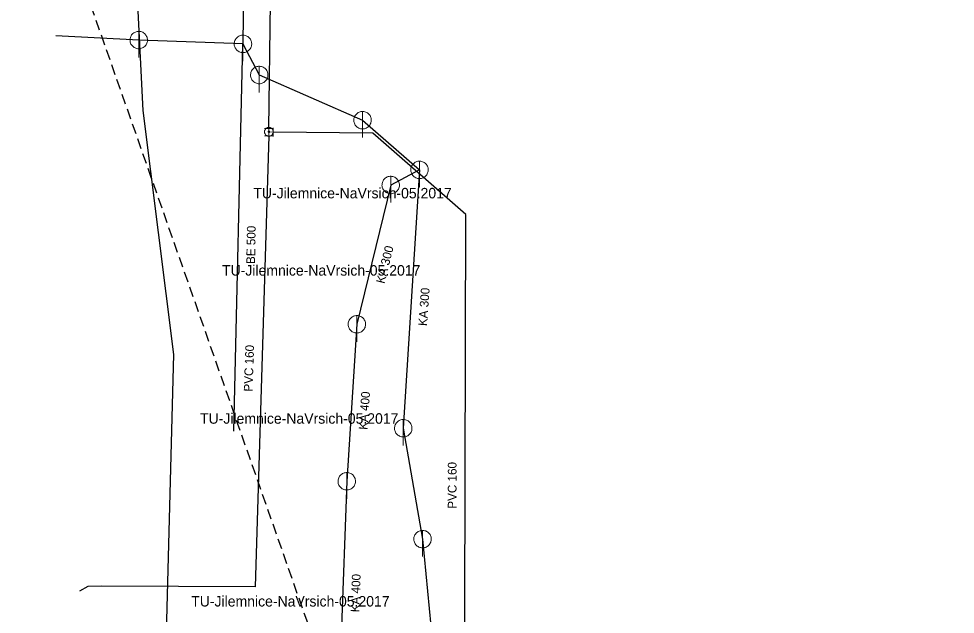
# Model space of a CAD drawing. Extents: x -659250 to -657316, y -997555 to -993684.
# Drawn here: x -658539.7 to -658432.4, y -995591.1 to -995522.9 of the extents above; entities that cross this region are included whole.
import ezdxf

# ---------------------------------------------------------------- set-up
doc = ezdxf.new("R2010")
doc.units = 0
doc.header["$LTSCALE"] = 0.4
doc.linetypes.add('MEDIUM_DASHED', pattern=[4.5, 3, -1.5])
doc.layers.add('1', color=7, linetype='Continuous')
for name, color, linetype, lineweight in [('14', 7, 'Continuous', 25), ('17', 7, 'Continuous', 25), ('22', 7, 'Continuous', 13), ('34', 7, 'Continuous', 13), ('47', 7, 'Continuous', 13), ('63', 7, 'MEDIUM_DASHED', 25)]:
    doc.layers.add(name, color=color, linetype=linetype, lineweight=lineweight)

msp = doc.modelspace()

# ---------------------------------------------------------------- linework, layer by layer
at = {"layer": '14'}
for p, q in [((-658515.1, -995570.149), (-658514.039, -995525.77)), ((-658514.039, -995525.77), (-658512.17, -995529.34)), ((-658512.17, -995529.34), (-658500.329, -995534.52)), ((-658500.329, -995534.52), (-658493.8, -995540.21)), ((-658493.8, -995540.21), (-658497.1, -995541.949)), ((-658493.8, -995540.21), (-658495.66, -995569.82)), ((-658497.1, -995541.949), (-658500.98, -995557.91)), ((-658500.98, -995557.91), (-658502.14, -995575.899)), ((-658495.66, -995569.82), (-658493.449, -995582.53)), ((-658502.14, -995575.899), (-658503, -995599.809)), ((-658493.449, -995582.53), (-658492.51, -995592.469))]:
    msp.add_line(p, q, dxfattribs=at)
at = {"layer": '14', "lineweight": 13}
msp.add_line((-658511.085, -995536.327), (-658511.068, -995535.851), dxfattribs=at)
at = {"layer": '14'}
msp.add_lwpolyline([(-658513.609, -995487.75), (-658514.039, -995525.77), (-658525.986, -995525.335), (-658535.481, -995524.836)], dxfattribs=at)
at = {"layer": '14', "lineweight": 13}
msp.add_lwpolyline([(-658510.582, -995535.879), (-658511.068, -995535.851), (-658511.067, -995535.467)], dxfattribs=at)
at = {"layer": '17'}
for points in [[(-658522.919, -995597.629), (-658521.967, -995561.364), (-658525.493, -995533.403), (-658526.434, -995514.37), (-658523.848, -995479.362), (-658526.669, -995461.504), (-658525.493, -995439.824), (-658524.877, -995415.208), (-658524.344, -995415.072)], [(-658511.067, -995535.467), (-658510.679, -995506.566), (-658511.949, -995476.057), (-658513.219, -995461.105), (-658519.998, -995427.785), (-658524.344, -995415.072)], [(-658511.085, -995536.327), (-658512.631, -995588.013), (-658530.219, -995587.906), (-658531.84, -995587.956), (-658532.794, -995588.487)], [(-658488.624, -995605.785), (-658488.504, -995545.309), (-658499.164, -995536.019), (-658510.582, -995535.879)]]:
    msp.add_lwpolyline(points, dxfattribs=at)
at = {"layer": '22'}
for p, q in [((-658525.986, -995527.336), (-658525.985, -995524.336)), ((-658514.039, -995527.77), (-658514.038, -995524.77)), ((-658512.17, -995531.34), (-658512.169, -995528.34)), ((-658500.329, -995536.52), (-658500.328, -995533.52)), ((-658493.8, -995542.21), (-658493.799, -995539.21)), ((-658497.1, -995543.949), (-658497.099, -995540.949)), ((-658500.98, -995559.91), (-658500.979, -995556.91)), ((-658495.66, -995571.82), (-658495.659, -995568.82)), ((-658502.14, -995577.899), (-658502.139, -995574.899)), ((-658493.449, -995584.53), (-658493.448, -995581.53))]:
    msp.add_line(p, q, dxfattribs=at)
for points in [[(-658524.986, -995525.336), (-658524.991, -995525.227), (-658525.009, -995525.119), (-658525.039, -995525.013), (-658525.079, -995524.912), (-658525.131, -995524.815), (-658525.193, -995524.725), (-658525.265, -995524.642), (-658525.345, -995524.568), (-658525.433, -995524.502), (-658525.527, -995524.447), (-658525.627, -995524.402), (-658525.732, -995524.369), (-658525.839, -995524.347), (-658525.948, -995524.337), (-658526.058, -995524.339), (-658526.166, -995524.353), (-658526.273, -995524.378), (-658526.376, -995524.415), (-658526.474, -995524.464), (-658526.566, -995524.522), (-658526.652, -995524.591), (-658526.729, -995524.668), (-658526.798, -995524.754), (-658526.857, -995524.846), (-658526.905, -995524.944), (-658526.942, -995525.047), (-658526.968, -995525.154), (-658526.982, -995525.262), (-658526.985, -995525.372), (-658526.975, -995525.481), (-658526.954, -995525.588), (-658526.92, -995525.692), (-658526.876, -995525.792), (-658526.821, -995525.887), (-658526.755, -995525.975), (-658526.681, -995526.055), (-658526.598, -995526.127), (-658526.508, -995526.189), (-658526.412, -995526.241), (-658526.31, -995526.282), (-658526.205, -995526.312), (-658526.097, -995526.33), (-658525.987, -995526.336), (-658525.878, -995526.33), (-658525.77, -995526.312), (-658525.665, -995526.283), (-658525.563, -995526.242), (-658525.466, -995526.19), (-658525.376, -995526.128), (-658525.293, -995526.057), (-658525.218, -995525.977), (-658525.153, -995525.889), (-658525.097, -995525.795), (-658525.053, -995525.695), (-658525.019, -995525.591), (-658524.997, -995525.483), (-658524.987, -995525.374)], [(-658513.039, -995525.77), (-658513.044, -995525.661), (-658513.062, -995525.553), (-658513.092, -995525.447), (-658513.132, -995525.346), (-658513.184, -995525.249), (-658513.246, -995525.159), (-658513.318, -995525.076), (-658513.398, -995525.002), (-658513.486, -995524.936), (-658513.58, -995524.881), (-658513.68, -995524.836), (-658513.785, -995524.803), (-658513.892, -995524.781), (-658514.001, -995524.771), (-658514.111, -995524.773), (-658514.219, -995524.787), (-658514.326, -995524.812), (-658514.429, -995524.849), (-658514.527, -995524.898), (-658514.619, -995524.956), (-658514.705, -995525.025), (-658514.782, -995525.102), (-658514.851, -995525.188), (-658514.91, -995525.28), (-658514.958, -995525.378), (-658514.995, -995525.481), (-658515.021, -995525.588), (-658515.035, -995525.696), (-658515.038, -995525.806), (-658515.028, -995525.915), (-658515.007, -995526.022), (-658514.973, -995526.126), (-658514.929, -995526.226), (-658514.874, -995526.321), (-658514.808, -995526.409), (-658514.734, -995526.489), (-658514.651, -995526.561), (-658514.561, -995526.623), (-658514.465, -995526.675), (-658514.363, -995526.716), (-658514.258, -995526.746), (-658514.15, -995526.764), (-658514.04, -995526.77), (-658513.931, -995526.764), (-658513.823, -995526.746), (-658513.718, -995526.717), (-658513.616, -995526.676), (-658513.519, -995526.624), (-658513.429, -995526.562), (-658513.346, -995526.491), (-658513.271, -995526.411), (-658513.206, -995526.323), (-658513.15, -995526.229), (-658513.106, -995526.129), (-658513.072, -995526.025), (-658513.05, -995525.917), (-658513.04, -995525.808)], [(-658511.17, -995529.34), (-658511.175, -995529.231), (-658511.193, -995529.123), (-658511.223, -995529.017), (-658511.263, -995528.916), (-658511.315, -995528.819), (-658511.377, -995528.729), (-658511.449, -995528.646), (-658511.529, -995528.572), (-658511.617, -995528.506), (-658511.711, -995528.451), (-658511.811, -995528.406), (-658511.916, -995528.373), (-658512.023, -995528.351), (-658512.132, -995528.341), (-658512.242, -995528.343), (-658512.35, -995528.357), (-658512.457, -995528.382), (-658512.56, -995528.419), (-658512.658, -995528.468), (-658512.75, -995528.526), (-658512.836, -995528.595), (-658512.913, -995528.672), (-658512.982, -995528.758), (-658513.041, -995528.85), (-658513.089, -995528.948), (-658513.126, -995529.051), (-658513.152, -995529.158), (-658513.166, -995529.266), (-658513.169, -995529.376), (-658513.159, -995529.485), (-658513.138, -995529.592), (-658513.104, -995529.696), (-658513.06, -995529.796), (-658513.005, -995529.891), (-658512.939, -995529.979), (-658512.865, -995530.059), (-658512.782, -995530.131), (-658512.692, -995530.193), (-658512.596, -995530.245), (-658512.494, -995530.286), (-658512.389, -995530.316), (-658512.281, -995530.334), (-658512.171, -995530.34), (-658512.062, -995530.334), (-658511.954, -995530.316), (-658511.849, -995530.287), (-658511.747, -995530.246), (-658511.65, -995530.194), (-658511.56, -995530.132), (-658511.477, -995530.061), (-658511.402, -995529.981), (-658511.337, -995529.893), (-658511.281, -995529.799), (-658511.237, -995529.699), (-658511.203, -995529.595), (-658511.181, -995529.487), (-658511.171, -995529.378)], [(-658499.329, -995534.52), (-658499.334, -995534.411), (-658499.352, -995534.303), (-658499.382, -995534.197), (-658499.422, -995534.096), (-658499.474, -995533.999), (-658499.536, -995533.909), (-658499.608, -995533.826), (-658499.688, -995533.752), (-658499.776, -995533.686), (-658499.87, -995533.631), (-658499.97, -995533.586), (-658500.075, -995533.553), (-658500.182, -995533.531), (-658500.291, -995533.521), (-658500.401, -995533.523), (-658500.509, -995533.537), (-658500.616, -995533.562), (-658500.719, -995533.599), (-658500.817, -995533.648), (-658500.909, -995533.706), (-658500.995, -995533.775), (-658501.072, -995533.852), (-658501.141, -995533.938), (-658501.2, -995534.03), (-658501.248, -995534.128), (-658501.285, -995534.231), (-658501.311, -995534.338), (-658501.325, -995534.446), (-658501.328, -995534.556), (-658501.318, -995534.665), (-658501.297, -995534.772), (-658501.263, -995534.876), (-658501.219, -995534.976), (-658501.164, -995535.071), (-658501.098, -995535.159), (-658501.024, -995535.239), (-658500.941, -995535.311), (-658500.851, -995535.373), (-658500.755, -995535.425), (-658500.653, -995535.466), (-658500.548, -995535.496), (-658500.44, -995535.514), (-658500.33, -995535.52), (-658500.221, -995535.514), (-658500.113, -995535.496), (-658500.008, -995535.467), (-658499.906, -995535.426), (-658499.809, -995535.374), (-658499.719, -995535.312), (-658499.636, -995535.241), (-658499.561, -995535.161), (-658499.496, -995535.073), (-658499.44, -995534.979), (-658499.396, -995534.879), (-658499.362, -995534.775), (-658499.34, -995534.667), (-658499.33, -995534.558)], [(-658492.8, -995540.21), (-658492.805, -995540.101), (-658492.823, -995539.993), (-658492.853, -995539.887), (-658492.893, -995539.786), (-658492.945, -995539.689), (-658493.007, -995539.599), (-658493.079, -995539.516), (-658493.159, -995539.442), (-658493.247, -995539.376), (-658493.341, -995539.321), (-658493.441, -995539.276), (-658493.546, -995539.243), (-658493.653, -995539.221), (-658493.762, -995539.211), (-658493.872, -995539.213), (-658493.98, -995539.227), (-658494.087, -995539.252), (-658494.19, -995539.289), (-658494.288, -995539.338), (-658494.38, -995539.396), (-658494.466, -995539.465), (-658494.543, -995539.542), (-658494.612, -995539.628), (-658494.671, -995539.72), (-658494.719, -995539.818), (-658494.756, -995539.921), (-658494.782, -995540.028), (-658494.796, -995540.136), (-658494.799, -995540.246), (-658494.789, -995540.355), (-658494.768, -995540.462), (-658494.734, -995540.566), (-658494.69, -995540.666), (-658494.635, -995540.761), (-658494.569, -995540.849), (-658494.495, -995540.929), (-658494.412, -995541.001), (-658494.322, -995541.063), (-658494.226, -995541.115), (-658494.124, -995541.156), (-658494.019, -995541.186), (-658493.911, -995541.204), (-658493.801, -995541.21), (-658493.692, -995541.204), (-658493.584, -995541.186), (-658493.479, -995541.157), (-658493.377, -995541.116), (-658493.28, -995541.064), (-658493.19, -995541.002), (-658493.107, -995540.931), (-658493.032, -995540.851), (-658492.967, -995540.763), (-658492.911, -995540.669), (-658492.867, -995540.569), (-658492.833, -995540.465), (-658492.811, -995540.357), (-658492.801, -995540.248)], [(-658496.1, -995541.949), (-658496.105, -995541.84), (-658496.123, -995541.732), (-658496.153, -995541.626), (-658496.193, -995541.525), (-658496.245, -995541.428), (-658496.307, -995541.338), (-658496.379, -995541.255), (-658496.459, -995541.181), (-658496.547, -995541.115), (-658496.641, -995541.06), (-658496.741, -995541.015), (-658496.846, -995540.982), (-658496.953, -995540.96), (-658497.062, -995540.95), (-658497.172, -995540.952), (-658497.28, -995540.966), (-658497.387, -995540.991), (-658497.49, -995541.028), (-658497.588, -995541.077), (-658497.68, -995541.135), (-658497.766, -995541.204), (-658497.843, -995541.281), (-658497.912, -995541.367), (-658497.971, -995541.459), (-658498.019, -995541.557), (-658498.056, -995541.66), (-658498.082, -995541.767), (-658498.096, -995541.875), (-658498.099, -995541.985), (-658498.089, -995542.094), (-658498.068, -995542.201), (-658498.034, -995542.305), (-658497.99, -995542.405), (-658497.935, -995542.5), (-658497.869, -995542.588), (-658497.795, -995542.668), (-658497.712, -995542.74), (-658497.622, -995542.802), (-658497.526, -995542.854), (-658497.424, -995542.895), (-658497.319, -995542.925), (-658497.211, -995542.943), (-658497.101, -995542.949), (-658496.992, -995542.943), (-658496.884, -995542.925), (-658496.779, -995542.896), (-658496.677, -995542.855), (-658496.58, -995542.803), (-658496.49, -995542.741), (-658496.407, -995542.67), (-658496.332, -995542.59), (-658496.267, -995542.502), (-658496.211, -995542.408), (-658496.167, -995542.308), (-658496.133, -995542.204), (-658496.111, -995542.096), (-658496.101, -995541.987)], [(-658499.98, -995557.91), (-658499.985, -995557.801), (-658500.003, -995557.693), (-658500.033, -995557.587), (-658500.073, -995557.486), (-658500.125, -995557.389), (-658500.187, -995557.299), (-658500.259, -995557.216), (-658500.339, -995557.142), (-658500.427, -995557.076), (-658500.521, -995557.021), (-658500.621, -995556.976), (-658500.726, -995556.943), (-658500.833, -995556.921), (-658500.942, -995556.911), (-658501.052, -995556.913), (-658501.16, -995556.927), (-658501.267, -995556.952), (-658501.37, -995556.989), (-658501.468, -995557.038), (-658501.56, -995557.096), (-658501.646, -995557.165), (-658501.723, -995557.242), (-658501.792, -995557.328), (-658501.851, -995557.42), (-658501.899, -995557.518), (-658501.936, -995557.621), (-658501.962, -995557.728), (-658501.976, -995557.836), (-658501.979, -995557.946), (-658501.969, -995558.055), (-658501.948, -995558.162), (-658501.914, -995558.266), (-658501.87, -995558.366), (-658501.815, -995558.461), (-658501.749, -995558.549), (-658501.675, -995558.629), (-658501.592, -995558.701), (-658501.502, -995558.763), (-658501.406, -995558.815), (-658501.304, -995558.856), (-658501.199, -995558.886), (-658501.091, -995558.904), (-658500.981, -995558.91), (-658500.872, -995558.904), (-658500.764, -995558.886), (-658500.659, -995558.857), (-658500.557, -995558.816), (-658500.46, -995558.764), (-658500.37, -995558.702), (-658500.287, -995558.631), (-658500.212, -995558.551), (-658500.147, -995558.463), (-658500.091, -995558.369), (-658500.047, -995558.269), (-658500.013, -995558.165), (-658499.991, -995558.057), (-658499.981, -995557.948)], [(-658494.66, -995569.82), (-658494.665, -995569.711), (-658494.683, -995569.603), (-658494.713, -995569.497), (-658494.753, -995569.396), (-658494.805, -995569.299), (-658494.867, -995569.209), (-658494.939, -995569.126), (-658495.019, -995569.052), (-658495.107, -995568.986), (-658495.201, -995568.931), (-658495.301, -995568.886), (-658495.406, -995568.853), (-658495.513, -995568.831), (-658495.622, -995568.821), (-658495.732, -995568.823), (-658495.84, -995568.837), (-658495.947, -995568.862), (-658496.05, -995568.899), (-658496.148, -995568.948), (-658496.24, -995569.006), (-658496.326, -995569.075), (-658496.403, -995569.152), (-658496.472, -995569.238), (-658496.531, -995569.33), (-658496.579, -995569.428), (-658496.616, -995569.531), (-658496.642, -995569.638), (-658496.656, -995569.746), (-658496.659, -995569.856), (-658496.649, -995569.965), (-658496.628, -995570.072), (-658496.594, -995570.176), (-658496.55, -995570.276), (-658496.495, -995570.371), (-658496.429, -995570.459), (-658496.355, -995570.539), (-658496.272, -995570.611), (-658496.182, -995570.673), (-658496.086, -995570.725), (-658495.984, -995570.766), (-658495.879, -995570.796), (-658495.771, -995570.814), (-658495.661, -995570.82), (-658495.552, -995570.814), (-658495.444, -995570.796), (-658495.339, -995570.767), (-658495.237, -995570.726), (-658495.14, -995570.674), (-658495.05, -995570.612), (-658494.967, -995570.541), (-658494.892, -995570.461), (-658494.827, -995570.373), (-658494.771, -995570.279), (-658494.727, -995570.179), (-658494.693, -995570.075), (-658494.671, -995569.967), (-658494.661, -995569.858)], [(-658501.14, -995575.899), (-658501.145, -995575.79), (-658501.163, -995575.682), (-658501.193, -995575.576), (-658501.233, -995575.475), (-658501.285, -995575.378), (-658501.347, -995575.288), (-658501.419, -995575.205), (-658501.499, -995575.131), (-658501.587, -995575.065), (-658501.681, -995575.01), (-658501.781, -995574.965), (-658501.886, -995574.932), (-658501.993, -995574.91), (-658502.102, -995574.9), (-658502.212, -995574.902), (-658502.32, -995574.916), (-658502.427, -995574.941), (-658502.53, -995574.978), (-658502.628, -995575.027), (-658502.72, -995575.085), (-658502.806, -995575.154), (-658502.883, -995575.231), (-658502.952, -995575.317), (-658503.011, -995575.409), (-658503.059, -995575.507), (-658503.096, -995575.61), (-658503.122, -995575.717), (-658503.136, -995575.825), (-658503.139, -995575.935), (-658503.129, -995576.044), (-658503.108, -995576.151), (-658503.074, -995576.255), (-658503.03, -995576.355), (-658502.975, -995576.45), (-658502.909, -995576.538), (-658502.835, -995576.618), (-658502.752, -995576.69), (-658502.662, -995576.752), (-658502.566, -995576.804), (-658502.464, -995576.845), (-658502.359, -995576.875), (-658502.251, -995576.893), (-658502.141, -995576.899), (-658502.032, -995576.893), (-658501.924, -995576.875), (-658501.819, -995576.846), (-658501.717, -995576.805), (-658501.62, -995576.753), (-658501.53, -995576.691), (-658501.447, -995576.62), (-658501.372, -995576.54), (-658501.307, -995576.452), (-658501.251, -995576.358), (-658501.207, -995576.258), (-658501.173, -995576.154), (-658501.151, -995576.046), (-658501.141, -995575.937)], [(-658492.449, -995582.53), (-658492.454, -995582.421), (-658492.472, -995582.313), (-658492.502, -995582.207), (-658492.542, -995582.106), (-658492.594, -995582.009), (-658492.656, -995581.919), (-658492.728, -995581.836), (-658492.808, -995581.762), (-658492.896, -995581.696), (-658492.99, -995581.641), (-658493.09, -995581.596), (-658493.195, -995581.563), (-658493.302, -995581.541), (-658493.411, -995581.531), (-658493.521, -995581.533), (-658493.629, -995581.547), (-658493.736, -995581.572), (-658493.839, -995581.609), (-658493.937, -995581.658), (-658494.029, -995581.716), (-658494.115, -995581.785), (-658494.192, -995581.862), (-658494.261, -995581.948), (-658494.32, -995582.04), (-658494.368, -995582.138), (-658494.405, -995582.241), (-658494.431, -995582.348), (-658494.445, -995582.456), (-658494.448, -995582.566), (-658494.438, -995582.675), (-658494.417, -995582.782), (-658494.383, -995582.886), (-658494.339, -995582.986), (-658494.284, -995583.081), (-658494.218, -995583.169), (-658494.144, -995583.249), (-658494.061, -995583.321), (-658493.971, -995583.383), (-658493.875, -995583.435), (-658493.773, -995583.476), (-658493.668, -995583.506), (-658493.56, -995583.524), (-658493.45, -995583.53), (-658493.341, -995583.524), (-658493.233, -995583.506), (-658493.128, -995583.477), (-658493.026, -995583.436), (-658492.929, -995583.384), (-658492.839, -995583.322), (-658492.756, -995583.251), (-658492.681, -995583.171), (-658492.616, -995583.083), (-658492.56, -995582.989), (-658492.516, -995582.889), (-658492.482, -995582.785), (-658492.46, -995582.677), (-658492.45, -995582.568)]]:
    msp.add_lwpolyline(points, close=True, dxfattribs=at)
at = {"layer": '34'}
for p, q in [((-658511.584, -995536.312), (-658510.585, -995536.342)), ((-658510.567, -995535.472), (-658511.566, -995535.46)), ((-658510.576, -995535.379), (-658510.588, -995536.378))]:
    msp.add_line(p, q, dxfattribs=at)
at = {"layer": '47'}
for points in [[(-658510.568, -995535.851), (-658510.571, -995535.799), (-658510.579, -995535.747), (-658510.593, -995535.697), (-658510.61, -995535.648), (-658510.635, -995535.601), (-658510.664, -995535.557), (-658510.696, -995535.517), (-658510.733, -995535.48), (-658510.774, -995535.447), (-658510.818, -995535.418), (-658510.865, -995535.394), (-658510.914, -995535.376), (-658510.963, -995535.362), (-658511.016, -995535.354), (-658511.068, -995535.351), (-658511.12, -995535.354), (-658511.172, -995535.362), (-658511.223, -995535.376), (-658511.271, -995535.394), (-658511.318, -995535.418), (-658511.362, -995535.447), (-658511.402, -995535.48), (-658511.44, -995535.517), (-658511.473, -995535.557), (-658511.5, -995535.601), (-658511.525, -995535.648), (-658511.544, -995535.697), (-658511.556, -995535.747), (-658511.565, -995535.799), (-658511.568, -995535.851), (-658511.565, -995535.903), (-658511.556, -995535.955), (-658511.544, -995536.006), (-658511.525, -995536.054), (-658511.5, -995536.101), (-658511.473, -995536.145), (-658511.44, -995536.186), (-658511.402, -995536.223), (-658511.362, -995536.256), (-658511.318, -995536.284), (-658511.271, -995536.308), (-658511.223, -995536.327), (-658511.172, -995536.34), (-658511.12, -995536.348), (-658511.068, -995536.351), (-658511.016, -995536.348), (-658510.963, -995536.34), (-658510.914, -995536.327), (-658510.865, -995536.308), (-658510.818, -995536.284), (-658510.774, -995536.256), (-658510.733, -995536.223), (-658510.696, -995536.186), (-658510.664, -995536.145), (-658510.635, -995536.101), (-658510.61, -995536.054), (-658510.593, -995536.006), (-658510.579, -995535.955), (-658510.571, -995535.903)], [(-658510.985, -995535.851), (-658510.985, -995535.842), (-658510.988, -995535.834), (-658510.99, -995535.826), (-658510.993, -995535.818), (-658510.997, -995535.81), (-658511.002, -995535.803), (-658511.007, -995535.796), (-658511.012, -995535.79), (-658511.02, -995535.785), (-658511.027, -995535.78), (-658511.034, -995535.776), (-658511.043, -995535.773), (-658511.051, -995535.771), (-658511.059, -995535.769), (-658511.068, -995535.769), (-658511.076, -995535.769), (-658511.085, -995535.771), (-658511.093, -995535.773), (-658511.101, -995535.776), (-658511.108, -995535.78), (-658511.115, -995535.785), (-658511.123, -995535.79), (-658511.129, -995535.796), (-658511.135, -995535.803), (-658511.139, -995535.81), (-658511.142, -995535.818), (-658511.146, -995535.826), (-658511.147, -995535.834), (-658511.15, -995535.842), (-658511.15, -995535.851), (-658511.15, -995535.86), (-658511.147, -995535.868), (-658511.146, -995535.876), (-658511.142, -995535.884), (-658511.139, -995535.892), (-658511.135, -995535.899), (-658511.129, -995535.906), (-658511.123, -995535.912), (-658511.115, -995535.918), (-658511.108, -995535.922), (-658511.101, -995535.926), (-658511.093, -995535.929), (-658511.085, -995535.931), (-658511.076, -995535.933), (-658511.068, -995535.933), (-658511.059, -995535.933), (-658511.051, -995535.931), (-658511.043, -995535.929), (-658511.034, -995535.926), (-658511.027, -995535.922), (-658511.02, -995535.918), (-658511.012, -995535.912), (-658511.007, -995535.906), (-658511.002, -995535.899), (-658510.997, -995535.892), (-658510.993, -995535.884), (-658510.99, -995535.876), (-658510.988, -995535.868), (-658510.985, -995535.86)]]:
    msp.add_lwpolyline(points, close=True, dxfattribs=at)
at = {"layer": '63'}
msp.add_lwpolyline([(-659116.685, -993855.266), (-658551.464, -993848.288), (-658551.464, -993848.288), (-657316.352, -997490.822), (-657316.352, -997490.822), (-657839.705, -997490.822), (-657839.705, -997490.822)], close=True, dxfattribs=at)

# ---------------------------------------------------------------- texts
at = {"layer": '1'}
for p in [(-658512.85, -995543.48), (-658516.44, -995552.33), (-658518.96, -995569.305), (-658519.97, -995590.254)]:
    msp.add_text('TU-Jilemnice-NaVrsich-05.2017 ', height=1.2, dxfattribs=at).set_placement(p)
for s, rotation, p in [('BE 500', 89, (-658512.656, -995551.006)), ('KA 300', 76, (-658497.818, -995553.313)), ('KA 300', 86, (-658492.936, -995558.133)), ('PVC 160 ', 88, (-658512.946, -995565.639)), ('KA 400', 86, (-658499.771, -995570.025)), ('PVC 160 ', 90, (-658489.555, -995579.044)), ('KA 400', 88, (-658500.693, -995590.924))]:
    msp.add_text(s, height=1, rotation=rotation, dxfattribs=at).set_placement(p)

doc.saveas('drawing.dxf')
